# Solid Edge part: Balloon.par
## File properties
Author: Indrek
Template: Normal.par
Last saved by: Indrek
Revision: 16
Application: Solid Edge
Density: 2795,000 kg/m^3
Accuracy: 0,990
Material: Aluminum, 7075-T6
Face Style: Aluminum
Fill Style: ANSI38(Aluminum)
Virtual Style: Polished aluminum
Coef. of Thermal Exp: 2.3e-05
Thermal Conductivity: 121.0
Specific Heat: 920.0
Modulus of Elasticity: 71705472800.0
Poission's Ratio: 0.33
Yield Stress: 503317261.0
Ultimate Stress: 572264831.0
Elongation: 0.0
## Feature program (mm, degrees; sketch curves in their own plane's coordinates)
make body feature "unnamed MakeBodyFeature 1"
sketch for "unnamed Cutout 1" plane through (0, 0, 0) normal (0, -1, 0) x-axis (1, 0, 0)
  line (253.2783, -199.2064) -> (-238.0348, -199.2064)
  line (-238.0348, -199.2064) -> (-238.0348, -307.2438)
  line (-238.0348, -307.2438) -> (253.2783, -307.2438)
  line (253.2783, -307.2438) -> (253.2783, -199.2064)
extrude "unnamed Cutout 1" cut finite 1049.3973 symmetric
sketch for "ExtrudedCutout_3" plane through (0, 0, -199.2064) normal (0, 0, -1) x-axis (1, 0, 0)
extrude "ExtrudedCutout_3" cut finite 2 along -normal
sketch for "ExtrudedCutout_4" plane through (0, 0, 0) normal (0, 0, 1) x-axis (1, 0, 0)
  line (-1, -0.2123) -> (0, -0.2123)
extrude "ExtrudedCutout_4" cut finite 426.4703 symmetric
thinwall "Thinwall_5"  Thickness = 2 mm
sketch used by "ExtrudedCutout_5" plane through (0, 500, 0.2123) normal (0, 1, 0) x-axis (-1, 0, 0)
extrude "ExtrudedCutout_5" cut finite 1 along -normal
sketch used by "ExtrudedProtrusion_1" plane through (0, 499, 0.2123) normal (0, 1, 0) x-axis (-1, 0, 0)
extrude "ExtrudedProtrusion_1" add finite 2 along +normal
sketch for "ExtrudedCutout_6" plane through (0, 500, 0.2123) normal (0, 1, 0) x-axis (-1, 0, 0)
extrude "ExtrudedCutout_6" cut finite 100 along -normal
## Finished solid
Body 1: solid body, 37 faces, 80 edges, 50 vertices, 2 separate solids.
  Faces by surface: plane 20, offset 8, spline 8, cylinder 1
  Edges by curve: line 38, intersection 29, spline 7, circle 6
Body 2: solid body, 8 faces, 12 edges, 6 vertices.
  Faces by surface: spline 8
  Edges by curve: spline 8, circle 4
Bounding box of the edges (mm; curved faces can reach further): 585.326 x 1435.527 x 577.923, from (-292.6628, -717.7634, -288.3515) to (292.6628, 717.7634, 289.571).
Cylindrical faces by radius (mm): R100.6788 x1
Planar faces by outward normal: +x 3, +y 4, +z 3, -x 3, -y 4, -z 3
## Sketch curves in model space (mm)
circle centre (0, 500, 0.2123) radius 100.6788
circle centre (0, 500, 0.2123) radius 38.8474
line (1, 499, 2) -> (0, 499, 2)
line (0, 499, 2) -> (0, 499, 0)
line (1, 499, 0) -> (0, 499, 0)
line (1, 499, 0) -> (1, 499, 2)
arc centre (-13.6069, 0, -18.0737) radius 306.6183 from (0, 0, 288.2425) through (207.9336, 0, 193.9041) to (292.4783, 0, 0)
spline (0, 717.7634, 0) -> (219.6102, 411.5079, 0) -> (292.4783, 0, 0)
spline (0, 0, 288.2425) -> (0, 509.0425, 195.77) -> (0, 717.7634, 0)
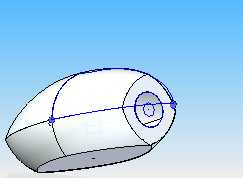
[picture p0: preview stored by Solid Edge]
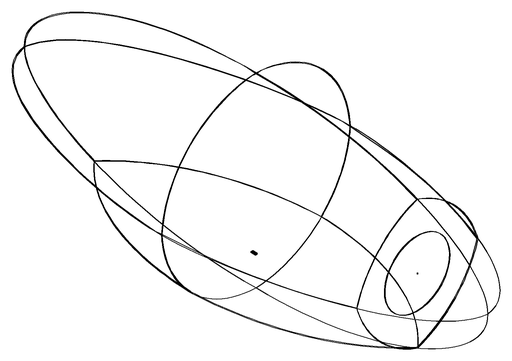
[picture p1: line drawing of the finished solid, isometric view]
